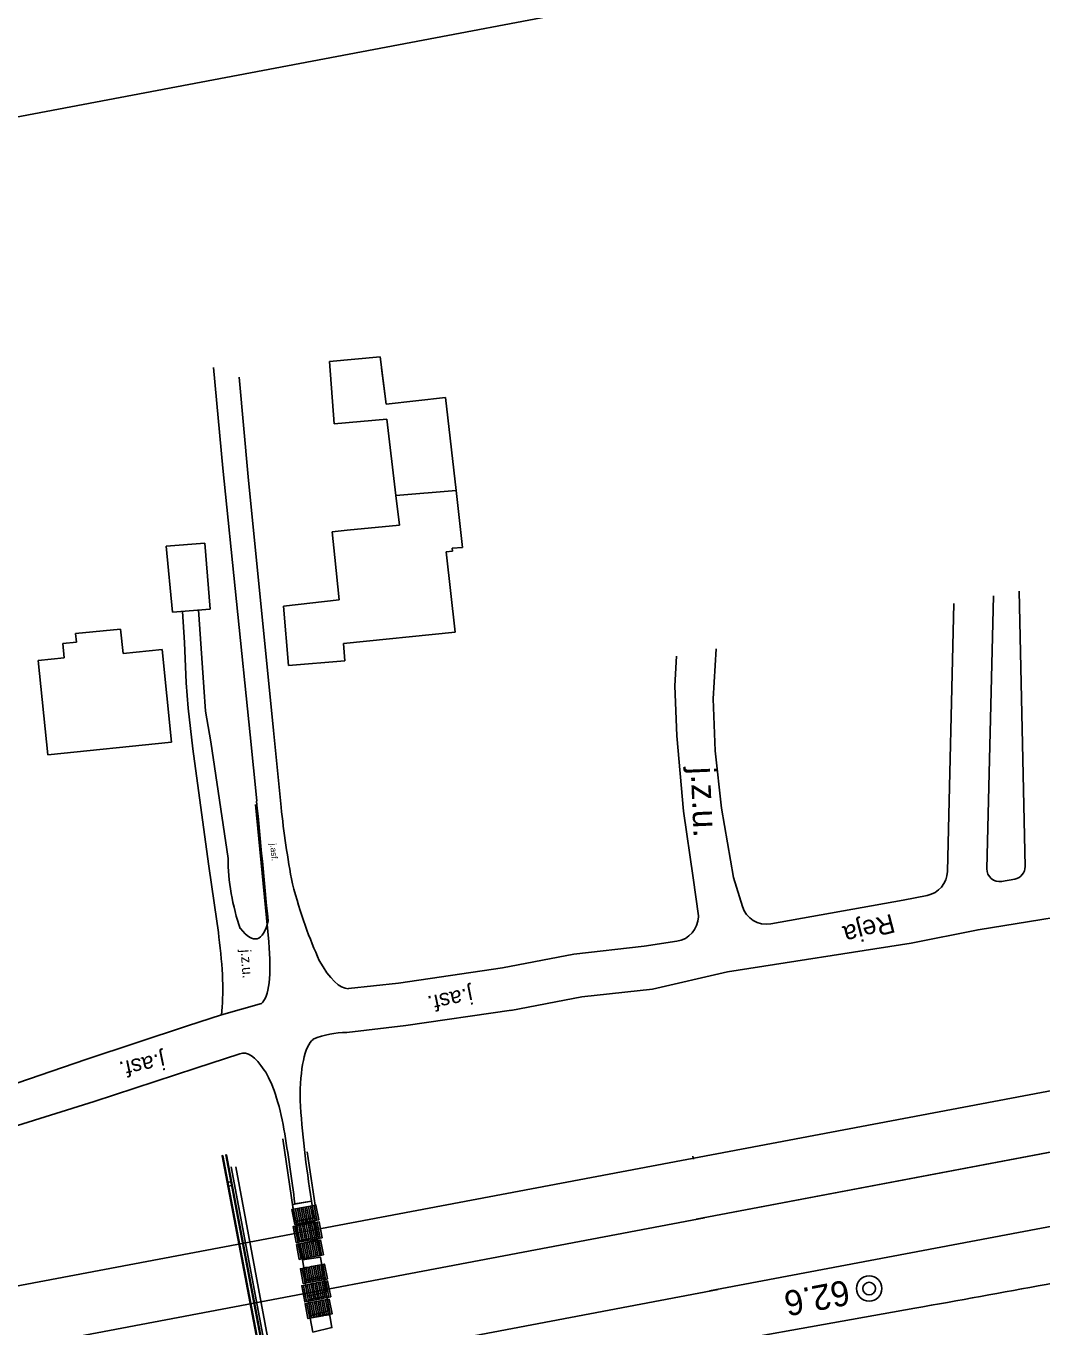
# Model space of a CAD drawing. Extents: x 6541740 to 6566395, y 5525066 to 5530361.
# Drawn here: x 6556863.5 to 6556944.2, y 5526109.6 to 5526213.1 of the extents above; entities that cross this region are included whole.
import ezdxf

# ---------------------------------------------------------------- set-up
doc = ezdxf.new("R2010")
doc.units = 0
for name, color, linetype in [('Domyślna', 7, 'Continuous'), ('ps_wymiarowanie', 7, 'Continuous'), ('TOR_PRZEK_P-komponent', 7, 'Continuous'), ('TOR_PRZEK_P-teren istniejacy', 7, 'Continuous'), ('TOR_PS_OPIS_T-symbole geometrii', 7, 'Continuous'), ('TOR_PS_P-chodniki i place ładunkowe', 7, 'Continuous'), ('TOR_PS_T-rowy otwarte nieumocnione', 7, 'Continuous'), ('TOR_PS_T-wypelnienia', 7, 'Continuous'), ('TOR_RAMKI-ramka+tabelka 1', 7, 'Continuous'), ('TOR_W-warstwa dodatkowa 2', 7, 'Continuous')]:
    doc.layers.add(name, color=color, linetype=linetype)

# ---------------------------------------------------------------- blocks, each defined once
blk = doc.blocks.new('4010_1')
at = {"layer": 'Domyślna'}
for radius in [0.75, 0.375]:
    blk.add_circle((0, 0), radius, dxfattribs=at)

msp = doc.modelspace()

# ---------------------------------------------------------------- linework, layer by layer
at = {"layer": 'Domyślna'}
msp.add_line((6556886.44, 5526114.54), (6556886.47, 5526114.5), dxfattribs=at)
for points in [[(6556885.12, 5526117.85), (6556884.9, 5526119.03), (6556884.75, 5526119.01), (6556884.97, 5526117.83)], [(6556885.27, 5526117.88), (6556885.05, 5526119.06), (6556884.9, 5526119.03), (6556885.12, 5526117.85)], [(6556885.42, 5526117.91), (6556885.19, 5526119.09), (6556885.05, 5526119.06), (6556885.27, 5526117.88)], [(6556885.56, 5526117.94), (6556885.34, 5526119.12), (6556885.19, 5526119.09), (6556885.42, 5526117.91)], [(6556885.71, 5526117.97), (6556885.49, 5526119.15), (6556885.34, 5526119.12), (6556885.56, 5526117.94)], [(6556885.86, 5526117.99), (6556885.63, 5526119.17), (6556885.49, 5526119.15), (6556885.71, 5526117.97)], [(6556886.01, 5526118.02), (6556885.78, 5526119.2), (6556885.63, 5526119.17), (6556885.86, 5526117.99)], [(6556886.15, 5526118.05), (6556885.93, 5526119.23), (6556885.78, 5526119.2), (6556886.01, 5526118.02)], [(6556886.3, 5526118.08), (6556886.08, 5526119.26), (6556885.93, 5526119.23), (6556886.15, 5526118.05)], [(6556886.45, 5526118.11), (6556886.22, 5526119.28), (6556886.08, 5526119.26), (6556886.3, 5526118.08)], [(6556886.59, 5526118.13), (6556886.37, 5526119.31), (6556886.22, 5526119.28), (6556886.45, 5526118.11)], [(6556886.74, 5526118.16), (6556886.52, 5526119.34), (6556886.37, 5526119.31), (6556886.59, 5526118.13)], [(6556884.97, 5526117.83), (6556884.75, 5526119.01), (6556884.6, 5526118.98), (6556884.83, 5526117.8)], [(6556887.01, 5526116.74), (6556886.77, 5526118.01), (6556886.62, 5526117.99), (6556886.87, 5526116.71)], [(6556885.1, 5526116.37), (6556884.85, 5526117.65), (6556884.71, 5526117.62), (6556884.95, 5526116.35)], [(6556885.24, 5526116.4), (6556885, 5526117.68), (6556884.85, 5526117.65), (6556885.1, 5526116.37)], [(6556885.39, 5526116.43), (6556885.15, 5526117.71), (6556885, 5526117.68), (6556885.24, 5526116.4)], [(6556885.54, 5526116.46), (6556885.3, 5526117.74), (6556885.15, 5526117.71), (6556885.39, 5526116.43)], [(6556885.69, 5526116.49), (6556885.44, 5526117.76), (6556885.3, 5526117.74), (6556885.54, 5526116.46)], [(6556885.83, 5526116.51), (6556885.59, 5526117.79), (6556885.44, 5526117.76), (6556885.69, 5526116.49)], [(6556885.98, 5526116.54), (6556885.74, 5526117.82), (6556885.59, 5526117.79), (6556885.83, 5526116.51)], [(6556886.13, 5526116.57), (6556885.89, 5526117.85), (6556885.74, 5526117.82), (6556885.98, 5526116.54)], [(6556886.28, 5526116.6), (6556886.03, 5526117.87), (6556885.89, 5526117.85), (6556886.13, 5526116.57)], [(6556886.42, 5526116.63), (6556886.18, 5526117.9), (6556886.03, 5526117.87), (6556886.28, 5526116.6)], [(6556886.57, 5526116.65), (6556886.33, 5526117.93), (6556886.18, 5526117.9), (6556886.42, 5526116.63)], [(6556886.72, 5526116.68), (6556886.48, 5526117.96), (6556886.33, 5526117.93), (6556886.57, 5526116.65)], [(6556886.87, 5526116.71), (6556886.62, 5526117.99), (6556886.48, 5526117.96), (6556886.72, 5526116.68)], [(6556885.12, 5526116.23), (6556885.35, 5526115.05), (6556885.2, 5526115.02), (6556884.98, 5526116.2)], [(6556885.27, 5526116.25), (6556885.5, 5526115.08), (6556885.35, 5526115.05), (6556885.12, 5526116.23)], [(6556885.42, 5526116.28), (6556885.64, 5526115.1), (6556885.5, 5526115.08), (6556885.27, 5526116.25)], [(6556885.57, 5526116.31), (6556885.79, 5526115.13), (6556885.64, 5526115.1), (6556885.42, 5526116.28)], [(6556885.71, 5526116.34), (6556885.94, 5526115.16), (6556885.79, 5526115.13), (6556885.57, 5526116.31)], [(6556885.86, 5526116.37), (6556886.08, 5526115.19), (6556885.94, 5526115.16), (6556885.71, 5526116.34)], [(6556886.01, 5526116.39), (6556886.23, 5526115.22), (6556886.08, 5526115.19), (6556885.86, 5526116.37)], [(6556886.16, 5526116.42), (6556886.38, 5526115.24), (6556886.23, 5526115.22), (6556886.01, 5526116.39)], [(6556886.3, 5526116.45), (6556886.53, 5526115.27), (6556886.38, 5526115.24), (6556886.16, 5526116.42)], [(6556886.45, 5526116.48), (6556886.67, 5526115.3), (6556886.53, 5526115.27), (6556886.3, 5526116.45)], [(6556886.6, 5526116.51), (6556886.82, 5526115.33), (6556886.67, 5526115.3), (6556886.45, 5526116.48)], [(6556886.75, 5526116.53), (6556886.97, 5526115.35), (6556886.82, 5526115.33), (6556886.6, 5526116.51)], [(6556886.89, 5526116.56), (6556887.12, 5526115.38), (6556886.97, 5526115.35), (6556886.75, 5526116.53)], [(6556885.66, 5526113.12), (6556885.43, 5526114.3), (6556885.29, 5526114.27), (6556885.51, 5526113.09)], [(6556885.81, 5526113.15), (6556885.58, 5526114.33), (6556885.43, 5526114.3), (6556885.66, 5526113.12)], [(6556885.95, 5526113.18), (6556885.73, 5526114.36), (6556885.58, 5526114.33), (6556885.81, 5526113.15)], [(6556886.1, 5526113.21), (6556885.88, 5526114.38), (6556885.73, 5526114.36), (6556885.95, 5526113.18)], [(6556886.25, 5526113.23), (6556886.02, 5526114.41), (6556885.88, 5526114.38), (6556886.1, 5526113.21)], [(6556886.39, 5526113.26), (6556886.17, 5526114.44), (6556886.02, 5526114.41), (6556886.25, 5526113.23)], [(6556886.54, 5526113.29), (6556886.32, 5526114.47), (6556886.17, 5526114.44), (6556886.39, 5526113.26)], [(6556886.69, 5526113.32), (6556886.47, 5526114.5), (6556886.32, 5526114.47), (6556886.54, 5526113.29)], [(6556886.84, 5526113.35), (6556886.61, 5526114.52), (6556886.47, 5526114.5), (6556886.69, 5526113.32)], [(6556886.98, 5526113.37), (6556886.76, 5526114.55), (6556886.61, 5526114.52), (6556886.84, 5526113.35)], [(6556887.13, 5526113.4), (6556886.91, 5526114.58), (6556886.76, 5526114.55), (6556886.98, 5526113.37)], [(6556887.28, 5526113.43), (6556887.06, 5526114.61), (6556886.91, 5526114.58), (6556887.13, 5526113.4)], [(6556887.43, 5526113.46), (6556887.2, 5526114.64), (6556887.06, 5526114.61), (6556887.28, 5526113.43)], [(6556885.78, 5526111.67), (6556885.54, 5526112.95), (6556885.39, 5526112.92), (6556885.63, 5526111.64)], [(6556885.93, 5526111.7), (6556885.69, 5526112.97), (6556885.54, 5526112.95), (6556885.78, 5526111.67)], [(6556886.08, 5526111.72), (6556885.83, 5526113), (6556885.69, 5526112.97), (6556885.93, 5526111.7)], [(6556886.22, 5526111.75), (6556885.98, 5526113.03), (6556885.83, 5526113), (6556886.08, 5526111.72)], [(6556886.37, 5526111.78), (6556886.13, 5526113.06), (6556885.98, 5526113.03), (6556886.22, 5526111.75)], [(6556886.52, 5526111.81), (6556886.28, 5526113.09), (6556886.13, 5526113.06), (6556886.37, 5526111.78)], [(6556886.66, 5526111.84), (6556886.42, 5526113.11), (6556886.28, 5526113.09), (6556886.52, 5526111.81)], [(6556886.81, 5526111.86), (6556886.57, 5526113.14), (6556886.42, 5526113.11), (6556886.66, 5526111.84)], [(6556886.96, 5526111.89), (6556886.72, 5526113.17), (6556886.57, 5526113.14), (6556886.81, 5526111.86)], [(6556887.11, 5526111.92), (6556886.86, 5526113.2), (6556886.72, 5526113.17), (6556886.96, 5526111.89)], [(6556887.25, 5526111.95), (6556887.01, 5526113.23), (6556886.86, 5526113.2), (6556887.11, 5526111.92)], [(6556887.4, 5526111.98), (6556887.16, 5526113.25), (6556887.01, 5526113.23), (6556887.25, 5526111.95)], [(6556887.55, 5526112), (6556887.31, 5526113.28), (6556887.16, 5526113.25), (6556887.4, 5526111.98)], [(6556887.7, 5526112.03), (6556887.45, 5526113.31), (6556887.31, 5526113.28), (6556887.55, 5526112)], [(6556887.28, 5526111.8), (6556887.51, 5526110.62), (6556887.36, 5526110.59), (6556887.13, 5526111.77)], [(6556887.43, 5526111.83), (6556887.65, 5526110.65), (6556887.51, 5526110.62), (6556887.28, 5526111.8)], [(6556887.58, 5526111.86), (6556887.8, 5526110.68), (6556887.65, 5526110.65), (6556887.43, 5526111.83)], [(6556885.81, 5526111.52), (6556886.03, 5526110.34), (6556885.88, 5526110.31), (6556885.66, 5526111.49)], [(6556885.96, 5526111.55), (6556886.18, 5526110.37), (6556886.03, 5526110.34), (6556885.81, 5526111.52)], [(6556886.1, 5526111.58), (6556886.33, 5526110.4), (6556886.18, 5526110.37), (6556885.96, 5526111.55)], [(6556886.25, 5526111.61), (6556886.47, 5526110.43), (6556886.33, 5526110.4), (6556886.1, 5526111.58)], [(6556886.4, 5526111.63), (6556886.62, 5526110.45), (6556886.47, 5526110.43), (6556886.25, 5526111.61)], [(6556886.55, 5526111.66), (6556886.77, 5526110.48), (6556886.62, 5526110.45), (6556886.4, 5526111.63)], [(6556886.69, 5526111.69), (6556886.92, 5526110.51), (6556886.77, 5526110.48), (6556886.55, 5526111.66)], [(6556886.84, 5526111.72), (6556887.06, 5526110.54), (6556886.92, 5526110.51), (6556886.69, 5526111.69)], [(6556886.99, 5526111.75), (6556887.21, 5526110.57), (6556887.06, 5526110.54), (6556886.84, 5526111.72)], [(6556887.13, 5526111.77), (6556887.36, 5526110.59), (6556887.21, 5526110.57), (6556886.99, 5526111.75)]]:
    msp.add_lwpolyline(points, close=True, dxfattribs=at)
at = {"layer": 'ps_wymiarowanie'}
for p, q in [((6556887.59, 5526186.42), (6556891.63, 5526186.79)), ((6556887.59, 5526186.42), (6556891.63, 5526186.79)), ((6556887.97, 5526181.47), (6556887.59, 5526186.42)), ((6556887.97, 5526181.47), (6556887.59, 5526186.42)), ((6556891.63, 5526186.79), (6556892.1, 5526183.05)), ((6556891.73, 5526185.89), (6556892.1, 5526183.05)), ((6556892.1, 5526183.05), (6556896.81, 5526183.58)), ((6556892.1, 5526183.05), (6556896.81, 5526183.58)), ((6556896.81, 5526183.58), (6556897.67, 5526176.17)), ((6556896.81, 5526183.58), (6556897.67, 5526176.17)), ((6556892.16, 5526181.85), (6556887.97, 5526181.47)), ((6556892.16, 5526181.85), (6556887.97, 5526181.47)), ((6556892.88, 5526175.77), (6556892.16, 5526181.85)), ((6556892.88, 5526175.77), (6556892.16, 5526181.85)), ((6556892.88, 5526175.77), (6556897.67, 5526176.17)), ((6556892.88, 5526175.77), (6556897.67, 5526176.17)), ((6556897.67, 5526176.17), (6556898.17, 5526171.65)), ((6556897.67, 5526176.17), (6556898.17, 5526171.65)), ((6556893.16, 5526173.41), (6556892.88, 5526175.77)), ((6556893.16, 5526173.41), (6556892.88, 5526175.77)), ((6556887.82, 5526172.88), (6556889.01, 5526173.02)), ((6556887.82, 5526172.88), (6556889.01, 5526173.02)), ((6556888.03, 5526170.85), (6556887.82, 5526172.88)), ((6556888.03, 5526170.85), (6556887.82, 5526172.88)), ((6556889.01, 5526173.02), (6556893.16, 5526173.41)), ((6556889.01, 5526173.02), (6556893.16, 5526173.41)), ((6556874.62, 5526171.74), (6556877.68, 5526171.99)), ((6556877.68, 5526171.99), (6556878.1, 5526166.74)), ((6556875.11, 5526166.5), (6556874.62, 5526171.74)), ((6556888.36, 5526167.47), (6556888.03, 5526170.85)), ((6556888.36, 5526167.47), (6556888.03, 5526170.85)), ((6556897.38, 5526171.34), (6556896.88, 5526171.28)), ((6556897.38, 5526171.34), (6556896.88, 5526171.28)), ((6556896.88, 5526171.28), (6556897.59, 5526164.89)), ((6556896.88, 5526171.28), (6556897.59, 5526164.89)), ((6556898.17, 5526171.65), (6556897.36, 5526171.59)), ((6556898.17, 5526171.65), (6556897.36, 5526171.59)), ((6556897.36, 5526171.59), (6556897.38, 5526171.34)), ((6556897.36, 5526171.59), (6556897.38, 5526171.34)), ((6556878.1, 5526166.74), (6556875.11, 5526166.5)), ((6556883.94, 5526166.96), (6556888.36, 5526167.47)), ((6556883.94, 5526166.96), (6556888.36, 5526167.47)), ((6556884.35, 5526162.24), (6556883.94, 5526166.96)), ((6556867.41, 5526164.79), (6556870.99, 5526165.14)), ((6556867.48, 5526164.11), (6556867.41, 5526164.79)), ((6556870.99, 5526165.14), (6556871.19, 5526163.21)), ((6556897.59, 5526164.89), (6556888.7, 5526164.01)), ((6556897.59, 5526164.89), (6556888.7, 5526164.01)), ((6556866.39, 5526164), (6556867.48, 5526164.11)), ((6556866.51, 5526162.87), (6556866.39, 5526164)), ((6556871.19, 5526163.21), (6556874.3, 5526163.53)), ((6556874.3, 5526163.53), (6556875.03, 5526156.15)), ((6556888.7, 5526164.01), (6556888.83, 5526162.63)), ((6556888.7, 5526164.01), (6556888.83, 5526162.63)), ((6556864.45, 5526162.66), (6556866.51, 5526162.87)), ((6556865.2, 5526155.16), (6556864.45, 5526162.66)), ((6556888.83, 5526162.63), (6556884.35, 5526162.24)), ((6556888.83, 5526162.63), (6556884.35, 5526162.24)), ((6556875.03, 5526156.15), (6556865.2, 5526155.16)), ((6556884.85, 5526119.43), (6556886.17, 5526119.66))]:
    msp.add_line(p, q, dxfattribs=at)
msp.add_lwpolyline([(6556913.27, 5526136.52), (6556919.25, 5526137.9), (6556933.84, 5526140.18), (6556939.16, 5526141.23), (6556950.28, 5526143.02)], dxfattribs=at)
at = {"layer": 'TOR_PRZEK_P-komponent'}
for p, q in [((6557012.57, 5526141.2), (6556792.18, 5526099.57)), ((6557036.44, 5526140.9), (6556916.74, 5526118.21)), ((6557032.88, 5526140.22), (6556916.74, 5526118.21)), ((6556992.9, 5526126.74), (6556917.82, 5526112.51)), ((6556992.9, 5526126.74), (6556917.82, 5526112.51)), ((6556917.42, 5526118.33), (6556766.92, 5526089.8)), ((6556918.5, 5526112.63), (6556528.95, 5526038.79)), ((6556934.13, 5526111.13), (6556912.79, 5526107.31))]:
    msp.add_line(p, q, dxfattribs=at)
msp.add_arc((6556571.47, 5528138.43), 2059.48, 280.14204, 280.73324, dxfattribs=at)
at = {"layer": 'TOR_PS_OPIS_T-symbole geometrii'}
for p, q in [((6556882.77, 5526140.28), (6556881.71, 5526151.2)), ((6556879.02, 5526134.46), (6556882.18, 5526135.37)), ((6556884.7, 5526119), (6556883.89, 5526124.61)), ((6556886.45, 5526119.33), (6556885.83, 5526123.56))]:
    msp.add_line(p, q, dxfattribs=at)
msp.add_ellipse((6556880.63, 5526142.4), major_axis=(1.35, -7.12), ratio=0.25, start_param=0.118115, end_param=1.220554, dxfattribs=at)
at = {"layer": 'TOR_PS_P-chodniki i place ładunkowe'}
msp.add_lwpolyline([(6558088.33, 5526146.08), (6556747.21, 5525891.87), (6556693.76, 5526173.84), (6558034.88, 5526428.06)], close=True, dxfattribs=at)
at = {"layer": 'TOR_PS_T-rowy otwarte nieumocnione'}
msp.add_line((6556916.49, 5526123.23), (6556916.53, 5526123), dxfattribs=at)
at = {"layer": 'TOR_PS_T-wypelnienia'}
for p, q in [((6556879.11, 5526177.96), (6556878.38, 5526185.95)), ((6556881.13, 5526177.27), (6556880.41, 5526185.18)), ((6556939.86, 5526146.09), (6556940.39, 5526167.78)), ((6556939.86, 5526146.09), (6556940.39, 5526167.78)), ((6556942.9, 5526146.27), (6556942.43, 5526168.16)), ((6556942.9, 5526146.27), (6556942.43, 5526168.16)), ((6556936.72, 5526145.87), (6556937.24, 5526167.18)), ((6556936.72, 5526145.87), (6556937.24, 5526167.18)), ((6556918.33, 5526163.59), (6556918.09, 5526159.59)), ((6556918.33, 5526163.59), (6556918.09, 5526159.59)), ((6556915.05, 5526160.63), (6556915.18, 5526163)), ((6556915.05, 5526160.63), (6556915.18, 5526163)), ((6556915.2, 5526156.65), (6556915.05, 5526160.63)), ((6556915.2, 5526156.65), (6556915.05, 5526160.63)), ((6556918.09, 5526159.59), (6556918.27, 5526155.46)), ((6556918.09, 5526159.59), (6556918.27, 5526155.46)), ((6556915.74, 5526150.67), (6556915.2, 5526156.65)), ((6556915.74, 5526150.67), (6556915.2, 5526156.65)), ((6556918.27, 5526155.46), (6556918.76, 5526150.9)), ((6556918.27, 5526155.46), (6556918.76, 5526150.9)), ((6556916.5, 5526145.37), (6556915.74, 5526150.67)), ((6556916.5, 5526145.37), (6556915.74, 5526150.67)), ((6556918.76, 5526150.9), (6556919.71, 5526145.4)), ((6556918.76, 5526150.9), (6556919.71, 5526145.4)), ((6556916.92, 5526142.34), (6556916.5, 5526145.37)), ((6556916.92, 5526142.34), (6556916.5, 5526145.37)), ((6556919.71, 5526145.4), (6556920.42, 5526143.08)), ((6556919.71, 5526145.4), (6556920.42, 5526143.08)), ((6556916.92, 5526142.27), (6556916.92, 5526142.34)), ((6556916.92, 5526142.27), (6556916.92, 5526142.34)), ((6556884.77, 5526095.75), (6556879.79, 5526122.37)), ((6556880.14, 5526122.39), (6556885.04, 5526096.11))]:
    msp.add_line(p, q, dxfattribs=at)
for points in [[(6556881.28, 5526156.73), (6556879.11, 5526177.96)], [(6556883.14, 5526157.07), (6556881.13, 5526177.27)], [(6556878.16, 5526156.19), (6556877.75, 5526158.63), (6556877.61, 5526160.54), (6556877.4, 5526163.6), (6556877.19, 5526166.67)], [(6556876.74, 5526155.62), (6556876.36, 5526158.87), (6556876.2, 5526160.88), (6556876.06, 5526164.09), (6556875.9, 5526166.56)], [(6556881.81, 5526151.48), (6556881.28, 5526156.73)], [(6556883.75, 5526150.98), (6556883.14, 5526157.07)], [(6556877.98, 5526146.48), (6556876.74, 5526155.62)], [(6556879.54, 5526146.89), (6556878.16, 5526156.19)], [(6556941.03, 5526145.08), (6556942.08, 5526145.27)], [(6556941.03, 5526145.08), (6556942.08, 5526145.27)], [(6556922.69, 5526141.7), (6556933.2, 5526143.58), (6556935.11, 5526143.96)], [(6556922.69, 5526141.7), (6556933.2, 5526143.58), (6556935.11, 5526143.96)], [(6556913.27, 5526136.52), (6556919.25, 5526137.9), (6556933.84, 5526140.18), (6556939.16, 5526141.23), (6556950.28, 5526143.02)], [(6556901.36, 5526138.2), (6556907.03, 5526139.3), (6556912.62, 5526139.94)], [(6556912.62, 5526139.94), (6556915.22, 5526140.32)], [(6556912.62, 5526139.94), (6556915.22, 5526140.32)], [(6556889.1, 5526136.55), (6556893.09, 5526136.98), (6556901.36, 5526138.2)], [(6556902.01, 5526134.8), (6556907.67, 5526135.9), (6556913.27, 5526136.52)], [(6556902.07, 5526134.83), (6556893.66, 5526133.63), (6556888.98, 5526133.06)], [(6556845.44, 5526123.34), (6556852.75, 5526125.61), (6556868.22, 5526130.92), (6556876.32, 5526133.58), (6556879.02, 5526134.46)], [(6556846.01, 5526120.38), (6556853.2, 5526122.67), (6556868.88, 5526127.58), (6556876.98, 5526130.23), (6556880.48, 5526131.37)]]:
    msp.add_lwpolyline(points, dxfattribs=at)
for points in [[(6556884.9, 5526118.04), (6556886.39, 5526118.31), (6556886.17, 5526119.66), (6556884.66, 5526119.37)], [(6556885.18, 5526116.5), (6556886.63, 5526116.81), (6556886.43, 5526118.04), (6556884.95, 5526117.76)], [(6556885.43, 5526115.1), (6556886.87, 5526115.33), (6556886.67, 5526116.58), (6556885.22, 5526116.25)], [(6556885.73, 5526113.42), (6556887.13, 5526113.7), (6556886.89, 5526115.19), (6556885.45, 5526114.98)], [(6556885.84, 5526112.1), (6556887.34, 5526112.41), (6556887.15, 5526113.56), (6556885.63, 5526113.29)], [(6556886.12, 5526110.56), (6556887.58, 5526110.92), (6556887.39, 5526112.11), (6556885.89, 5526111.8)], [(6556886.27, 5526109.23), (6556887.79, 5526109.59), (6556887.61, 5526110.68), (6556886.07, 5526110.33)]]:
    msp.add_lwpolyline(points, close=True, dxfattribs=at)
for centre, radius, start, end in [((6556940.86, 5526146.06), 1, 178.5979, 280.2186), ((6556940.86, 5526146.06), 1, 178.5979, 280.2186), ((6556941.9, 5526146.25), 1, 280.2186, 1.2166), ((6556941.9, 5526146.25), 1, 280.2186, 1.2166), ((6556934.72, 5526145.92), 2, 281.2145, 358.5979), ((6556934.72, 5526145.92), 2, 281.2145, 358.5979), ((6556922.33, 5526143.67), 2, 197.0334, 280.2186), ((6556922.33, 5526143.67), 2, 197.0334, 280.2186), ((6556914.92, 5526142.3), 2, 278.4537, 359.0122), ((6556914.92, 5526142.3), 2, 278.4537, 359.0122)]:
    msp.add_arc(centre, radius, start, end, dxfattribs=at)
for centre, major_axis, ratio, start_param, end_param in [((6556879.56, 5526149.59), (-13.99, 145.93), 0.016455, 4.658323, 4.7237), ((6556889.43, 5526145.81), (3.62, -19.15), 0.249699, 4.392121, 4.713095), ((6556866.37, 5526146.75), (9.75, -61.74), 0.18292, 1.443013, 1.537468), ((6556880.99, 5526144.09), (-0.88, 4.63), 0.2508, 0.876526, 2.157657), ((6556887.4, 5526149.83), (2.83, -14.87), 0.249614, 5.003407, 5.499821), ((6556880, 5526149.96), (-1.8, 9.45), 0.250296, 2.670315, 3.654221), ((6556875.69, 5526142.55), (2.06, -10.93), 0.25023, 0.69147, 1.349512), ((6556886.75, 5526149.64), (2.48, -13.08), 0.250015, 5.640362, 6.242529), ((6556888.77, 5526121.52), (-2.12, 11.16), 0.250016, 0.130532, 0.942311), ((6556909.89, 5526015.75), (22.19, -117.19), 0.250168, 3.098613, 3.190084), ((6556882.79, 5526120.06), (-2.15, 11.36), 0.250406, 5.741032, 6.339513), ((6556882.64, 5526125.55), (0.95, -5.03), 0.25, 1.489377, 2.639519), ((6556891.76, 5526118.56), (4.03, -21.96), 0.238412, 4.241962, 4.61874), ((6556873.49, 5526127.01), (-7.47, 39.45), 0.250001, 4.471942, 4.623752)]:
    msp.add_ellipse(centre, major_axis=major_axis, ratio=ratio, start_param=start_param, end_param=end_param, dxfattribs=at)
at = {"layer": 'TOR_W-warstwa dodatkowa 2'}
for points in [[(6556884.49, 5526094.88), (6556879.11, 5526123.27), (6556879.06, 5526123.26), (6556884.44, 5526094.87), (6556884.49, 5526094.88)], [(6556884.73, 5526094.92), (6556884.78, 5526094.93), (6556879.4, 5526123.33), (6556879.35, 5526123.32), (6556884.73, 5526094.92)], [(6556879.46, 5526121.13), (6556879.8, 5526121.2)], [(6556879.51, 5526120.84), (6556879.86, 5526120.9)]]:
    msp.add_lwpolyline(points, dxfattribs=at)

# ---------------------------------------------------------------- block references
at = {"layer": 'TOR_RAMKI-ramka+tabelka 1', "xscale": 1.345963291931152, "yscale": 1.345963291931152}
msp.add_blockref('4010_1', (6556930.5, 5526112.7), dxfattribs=at)

# ---------------------------------------------------------------- texts
at = {"layer": 'TOR_PRZEK_P-teren istniejacy'}
for s, height, rotation, p in [('j.z.u.', 1.991, 272.4647, (6556916.31, 5526154.15)), ('j.z.u.', 1.991, 272.4647, (6556916.31, 5526154.15)), ('Reja', 1.5, 194.5979, (6556932.3, 5526142.52)), ('Reja', 1.5, 194.5979, (6556932.3, 5526142.52))]:
    msp.add_text(s, height=height, rotation=rotation, dxfattribs=at).set_placement(p)
at = {"layer": 'TOR_PS_T-wypelnienia'}
for s, height, rotation, p in [('j.asf.', 0.49, 276.0396, (6556882.87, 5526148.07)), ('j.z.u.', 0.815, 274.4265, (6556880.53, 5526139.63)), ('j.asf.', 1.282, 191.5471, (6556898.85, 5526136.65)), ('j.asf.', 1.295, 191.7072, (6556874.37, 5526131.44))]:
    msp.add_text(s, height=height, rotation=rotation, dxfattribs=at).set_placement(p)
at = {"layer": 'TOR_RAMKI-ramka+tabelka 1'}
msp.add_text('62.6', height=2, rotation=190.7691, dxfattribs=at).set_placement((6556928.73, 5526113.41))

doc.saveas('drawing.dxf')
